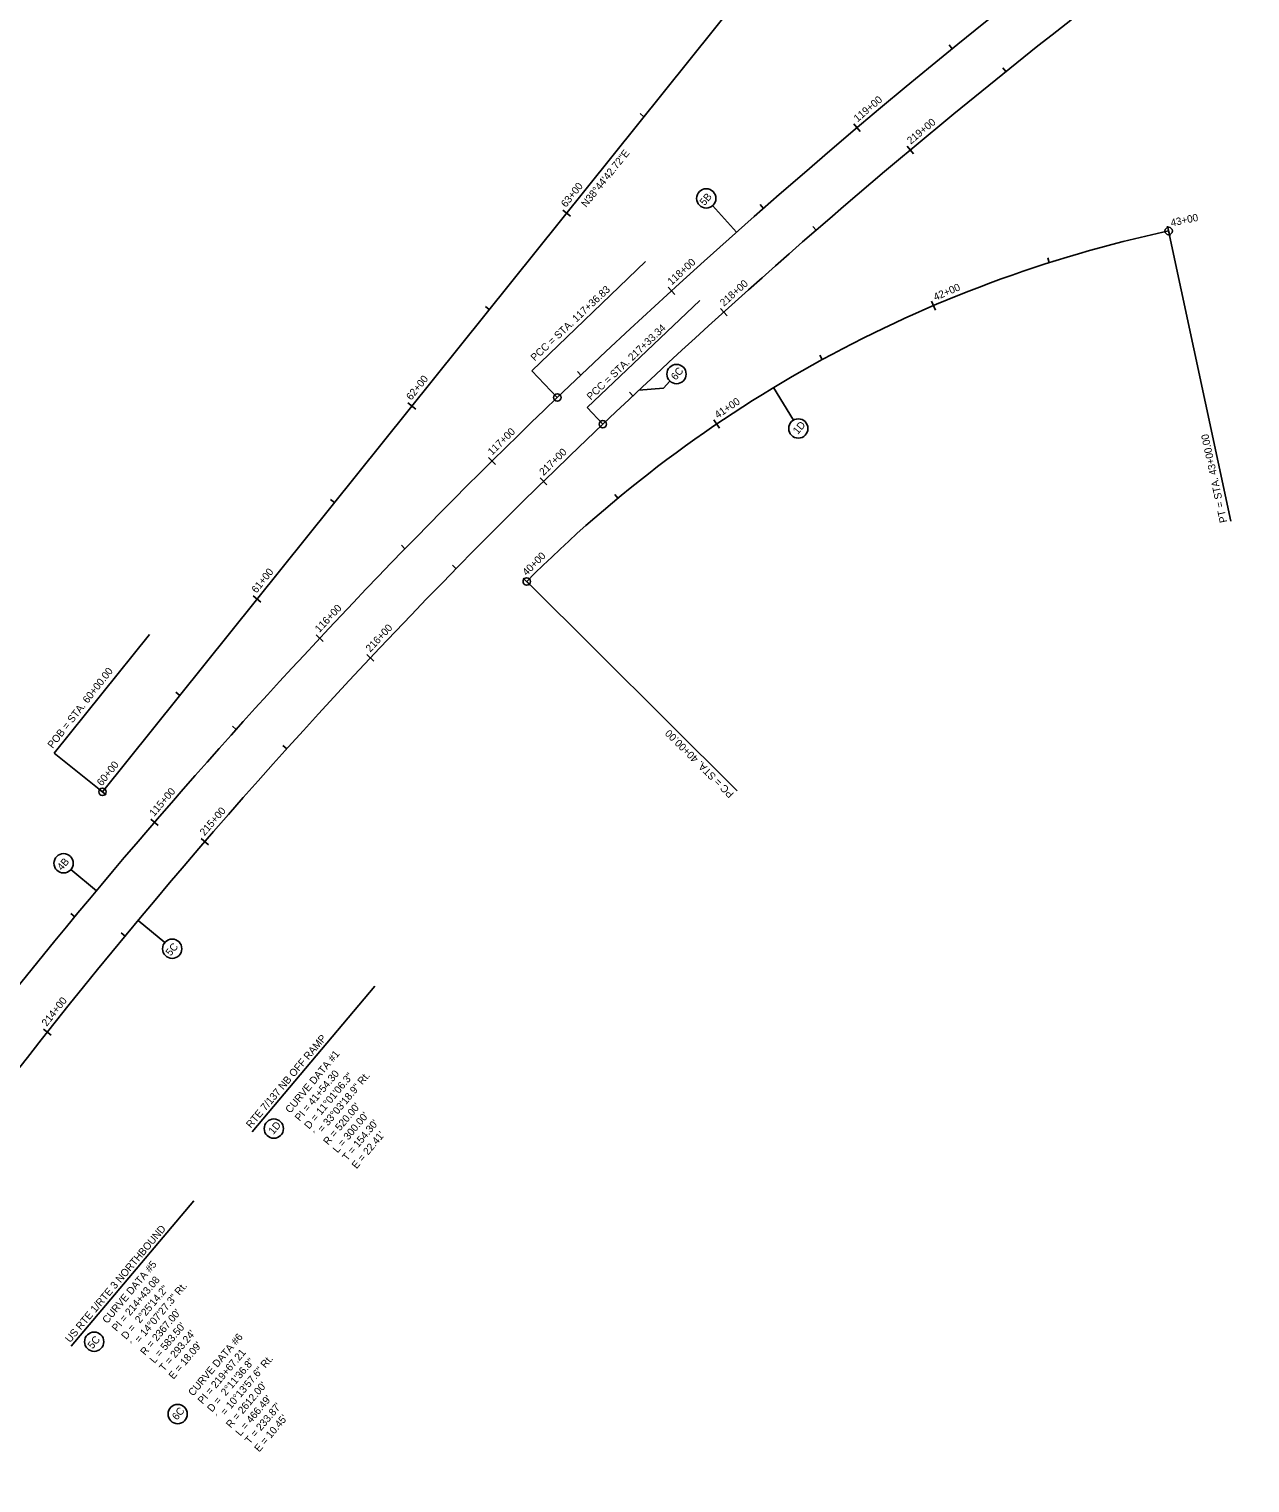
# Model space of a CAD drawing. Extents: x 1667099 to 1669772, y 337408 to 340124.
# Drawn here: x 1667798 to 1668292, y 338722 to 339310 of the extents above; entities that cross this region are included whole.
import ezdxf

# ---------------------------------------------------------------- set-up
doc = ezdxf.new("R2010")
doc.units = 0
for name, color, linetype in [('Alignment', 7, 'Continuous'), ('ANNOTATION', 7, 'Continuous'), ('D_Roadway_Centerline', 7, 'Continuous'), ('D_Roadway_Centerline_Bearings', 7, 'Continuous'), ('D_Roadway_Centerline_CurveData', 7, 'Continuous'), ('D_Roadway_Centerline_Flags', 7, 'Continuous'), ('D_Roadway_Centerline_Text', 7, 'Continuous'), ('Default', 7, 'Continuous'), ('S_Roadway_Edge_Pavement', 7, 'Continuous')]:
    doc.layers.add(name, color=color, linetype=linetype)

msp = doc.modelspace()

# ---------------------------------------------------------------- linework, layer by layer
at = {"layer": 'Alignment'}
for centre, radius, start, end in [((1669829.28, 337256.22), 2612, 123.30352, 133.53618), ((1669660.52, 337433.83), 2367, 133.53618, 147.66044)]:
    msp.add_arc(centre, radius, start, end, dxfattribs=at)
at = {"layer": 'ANNOTATION'}
for p, q in [((1668074.54, 339238.12), (1668084.12, 339227.34)), ((1668057.26, 339167.16), (1668054.59, 339164.29)), ((1668054.59, 339164.29), (1668044.65, 339163.47)), ((1668107.18, 339151.35), (1668099.21, 339164.55)), ((1667814.95, 338969.67), (1667825.21, 338961.09)), ((1667852.9, 338940.12), (1667842.11, 338949.11)), ((1667888.21, 338863.65), (1667937.81, 338922.44)), ((1667815.06, 338776.93), (1667864.66, 338835.72))]:
    msp.add_line(p, q, dxfattribs=at)
for centre in [(1668071.95, 339241.04), (1668059.92, 339170.01), (1668109.19, 339148.01), (1667811.96, 338972.18), (1667855.9, 338937.63), (1667897.01, 338864.9), (1667824.33, 338778.74), (1667858.11, 338749.49)]:
    msp.add_circle(centre, 3.9, dxfattribs=at)
at = {"layer": 'D_Roadway_Centerline'}
msp.add_line((1667827.67, 339001.09), (1668140.6, 339391.06), dxfattribs=at)
for centre, radius, start, end in [((1669819.48, 337273.8), 2613, 114.83733, 133.776), ((1669829.28, 337256.22), 2612, 123.30352, 133.53618), ((1668368, 338719.41), 520, 102.09882, 135.15408), ((1669733, 337364.06), 2488, 133.776, 144.54079), ((1669660.52, 337433.83), 2367, 133.53618, 147.66044)]:
    msp.add_arc(centre, radius, start, end, dxfattribs=at)
at = {"layer": 'D_Roadway_Centerline_Flags'}
for p, q in [((1668001.32, 339171.35), (1668047.41, 339215.51)), ((1668023.73, 339156.47), (1668069.31, 339199.78)), ((1667846.69, 339064.73), (1667808.17, 339016.74))]:
    msp.add_line(p, q, dxfattribs=at)
for points in [[(1668259.01, 339227.86), (1668284.16, 339110.53)], [(1668001.32, 339171.35), (1668011.7, 339160.52)], [(1668023.73, 339156.47), (1668030.1, 339149.76)], [(1667999.32, 339086.12), (1668084.4, 339001.49)], [(1667827.67, 339001.09), (1667808.17, 339016.74)]]:
    msp.add_lwpolyline(points, dxfattribs=at)
for centre in [(1668259.01, 339227.86), (1668011.7, 339160.52), (1668030.1, 339149.76), (1667999.32, 339086.12), (1667827.67, 339001.09)]:
    msp.add_circle(centre, 1.5, dxfattribs=at)
at = {"layer": 'D_Roadway_Centerline_Text'}
for points in [[(1668170.2, 339303.11), (1668171.46, 339301.56)], [(1668191.92, 339293.87), (1668193.17, 339292.32)], [(1668045.16, 339275.32), (1668046.72, 339274.07)], [(1668131.67, 339271.18), (1668134.25, 339268.13)], [(1668153.21, 339262.16), (1668155.78, 339259.09)], [(1668093.76, 339238.52), (1668095.08, 339237.02)], [(1668013.87, 339236.32), (1668016.99, 339233.82)], [(1668115.12, 339229.71), (1668116.44, 339228.2)], [(1668258.59, 339229.82), (1668259.43, 339225.91)], [(1668210.1, 339216.96), (1668210.7, 339215.05)], [(1668056.48, 339205.14), (1668059.18, 339202.19)], [(1667982.58, 339197.33), (1667984.14, 339196.08)], [(1668077.66, 339196.54), (1668080.34, 339193.57)], [(1668163.06, 339199.5), (1668164.63, 339195.82)], [(1668117.91, 339177.61), (1668118.87, 339175.85)], [(1668019.85, 339171.06), (1668021.23, 339169.6)], [(1668040.84, 339162.65), (1668042.21, 339161.2)], [(1667951.28, 339158.33), (1667954.4, 339155.83)], [(1668075.08, 339151.48), (1668077.33, 339148.17)], [(1667983.89, 339136.26), (1667986.7, 339133.42)], [(1668004.69, 339128.05), (1668007.49, 339125.19)], [(1668034.95, 339121.36), (1668036.23, 339119.82)], [(1667919.99, 339119.33), (1667921.55, 339118.08)], [(1667948.63, 339100.76), (1667950.06, 339099.36)], [(1667969.28, 339092.7), (1667970.71, 339091.3)], [(1667997.9, 339087.53), (1668000.74, 339084.71)], [(1667888.7, 339080.34), (1667891.82, 339077.83)], [(1667914.09, 339064.55), (1667917.01, 339061.82)], [(1667934.62, 339056.61), (1667937.53, 339053.87)], [(1667857.4, 339041.34), (1667858.96, 339040.09)], [(1667880.28, 339027.66), (1667881.77, 339026.32)], [(1667900.72, 339019.79), (1667902.21, 339018.45)], [(1667826.11, 339002.34), (1667829.23, 338999.84)], [(1667847.23, 338990.09), (1667850.26, 338987.48)], [(1667867.62, 338982.27), (1667870.65, 338979.65)], [(1667814.93, 338951.87), (1667816.47, 338950.59)], [(1667835.31, 338944.05), (1667836.85, 338942.78)], [(1667803.82, 338905.16), (1667806.95, 338902.68)]]:
    msp.add_lwpolyline(points, dxfattribs=at)
at = {"layer": 'Default'}
msp.add_line((1667827.67, 339001.09), (1668140.6, 339391.06), dxfattribs=at)
msp.add_arc((1668368, 338719.41), 520, 102.09882, 135.15408, dxfattribs=at)
at = {"layer": 'S_Roadway_Edge_Pavement'}
for centre, radius, start, end in [((1669819.48, 337273.8), 2613, 114.83733, 133.776), ((1669733, 337364.06), 2488, 133.776, 144.54079)]:
    msp.add_arc(centre, radius, start, end, dxfattribs=at)

# ---------------------------------------------------------------- texts
at = {"layer": 'ANNOTATION'}
for s, p in [('5B', (1668071.27, 339237.88)), ('6C', (1668059.63, 339167.3)), ('1D', (1668109, 339145.41)), ('4B', (1667811.29, 338969.02)), ('5C', (1667855.23, 338934.47)), ('RTE 7/137 NB OFF RAMP', (1667887.75, 338864.87)), ('1D', (1667896.81, 338862.31)), ('US RTE 1/RTE 3 NORTHBOUND', (1667814.6, 338778.15)), ('5C', (1667823.66, 338775.59)), ('6C', (1667857.81, 338746.78))]:
    msp.add_text(s, height=3, rotation=49.8502, dxfattribs=at).set_placement(p)
at = {"layer": 'D_Roadway_Centerline_Bearings'}
msp.add_text('N38%%d44\'42.72"E', height=3, rotation=51.2548, dxfattribs=at).set_placement((1668023.4, 339237.19))
at = {"layer": 'D_Roadway_Centerline_CurveData'}
for s, rotation, p in [('CURVE DATA #1', 50.06871, (1667903.65, 338870.88)), ('PI = 41+54.30', 50.06871, (1667907.48, 338867.67)), ('D = 11%%d01\'06.3"', 50.06871, (1667911.32, 338864.46)), ('´ = 33%%d03\'18.9" Rt.', 50.06871, (1667915.15, 338861.25)), ("R = 520.00'", 50.06871, (1667918.99, 338858.04)), ("L = 300.00'", 50.06871, (1667922.82, 338854.83)), ("T = 154.30'", 50.06871, (1667926.66, 338851.62)), ("E = 22.41'", 50.06871, (1667930.49, 338848.41)), ('CURVE DATA #5', 49.97318, (1667829.62, 338785.83)), ('PI = 214+43.08', 49.97318, (1667833.45, 338782.62)), ('D =  2%%d25\'14.2"', 49.97318, (1667837.28, 338779.4)), ('´ = 14%%d07\'27.3" Rt.', 49.97318, (1667841.11, 338776.19)), ("R = 2367.00'", 49.97318, (1667844.94, 338772.97)), ("L = 583.50'", 49.97318, (1667848.77, 338769.76)), ("T = 293.24'", 49.97318, (1667852.6, 338766.54)), ("E = 18.09'", 49.97318, (1667856.43, 338763.32)), ('CURVE DATA #6', 49.7757, (1667864.37, 338756.51)), ('PI = 219+67.21', 49.7757, (1667868.19, 338753.28)), ('D =  2%%d11\'36.8"', 49.7757, (1667872, 338750.05)), ('´ = 10%%d13\'57.6" Rt.', 49.7757, (1667875.82, 338746.82)), ("R = 2612.00'", 49.7757, (1667879.64, 338743.6)), ("L = 466.49'", 49.7757, (1667883.46, 338740.37)), ("T = 233.87'", 49.7757, (1667887.27, 338737.14)), ("E = 10.45'", 49.7757, (1667891.09, 338733.91))]:
    msp.add_text(s, height=3, rotation=rotation, dxfattribs=at).set_placement(p)
at = {"layer": 'D_Roadway_Centerline_Flags'}
for s, rotation, p in [('PCC = STA. 117+36.83', 43.2155, (1668002.61, 339175.01)), ('PCC = STA. 217+33.34', 43.5425, (1668025.3, 339159.26)), ('PT = STA. 43+00.00', 102.09882, (1668282.7, 339110.21)), ('POB = STA. 60+00.00', 52.00413, (1667807.54, 339018.42)), ('PC = STA. 40+00.00', 135.15408, (1668083.34, 339000.43))]:
    msp.add_text(s, height=3, rotation=rotation, dxfattribs=at).set_placement(p)
at = {"layer": 'D_Roadway_Centerline_Text'}
for s, rotation, p in [('119+00', 40.19823, (1668133.14, 339271.77)), ('219+00', 39.88049, (1668154.69, 339262.74)), ('63+00', 51.2548, (1668015.2, 339237.18)), ('43+00', 12.09882, (1668260.16, 339229.64)), ('118+00', 42.39095, (1668057.93, 339205.78)), ('218+00', 42.07405, (1668079.11, 339197.17)), ('42+00', 23.11724, (1668164.64, 339199.63)), ('62+00', 51.2548, (1667952.61, 339159.19)), ('41+00', 34.13566, (1668076.6, 339151.91)), ('117+00', 44.62425, (1667985.31, 339136.96)), ('217+00', 44.34331, (1668006.12, 339128.74)), ('40+00', 45.15408, (1667999.32, 339088.24)), ('61+00', 51.2548, (1667890.03, 339081.19)), ('116+00', 46.92714, (1667915.48, 339065.3)), ('216+00', 46.76392, (1667936.01, 339057.36)), ('60+00', 51.2548, (1667827.44, 339003.2)), ('115+00', 49.23002, (1667848.59, 338990.9)), ('215+00', 49.18453, (1667868.98, 338983.08)), ('214+00', 51.60513, (1667805.14, 338906.03))]:
    msp.add_text(s, height=3, rotation=rotation, dxfattribs=at).set_placement(p)

doc.saveas('drawing.dxf')
